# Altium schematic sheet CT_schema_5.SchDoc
size 300 x 247 mm
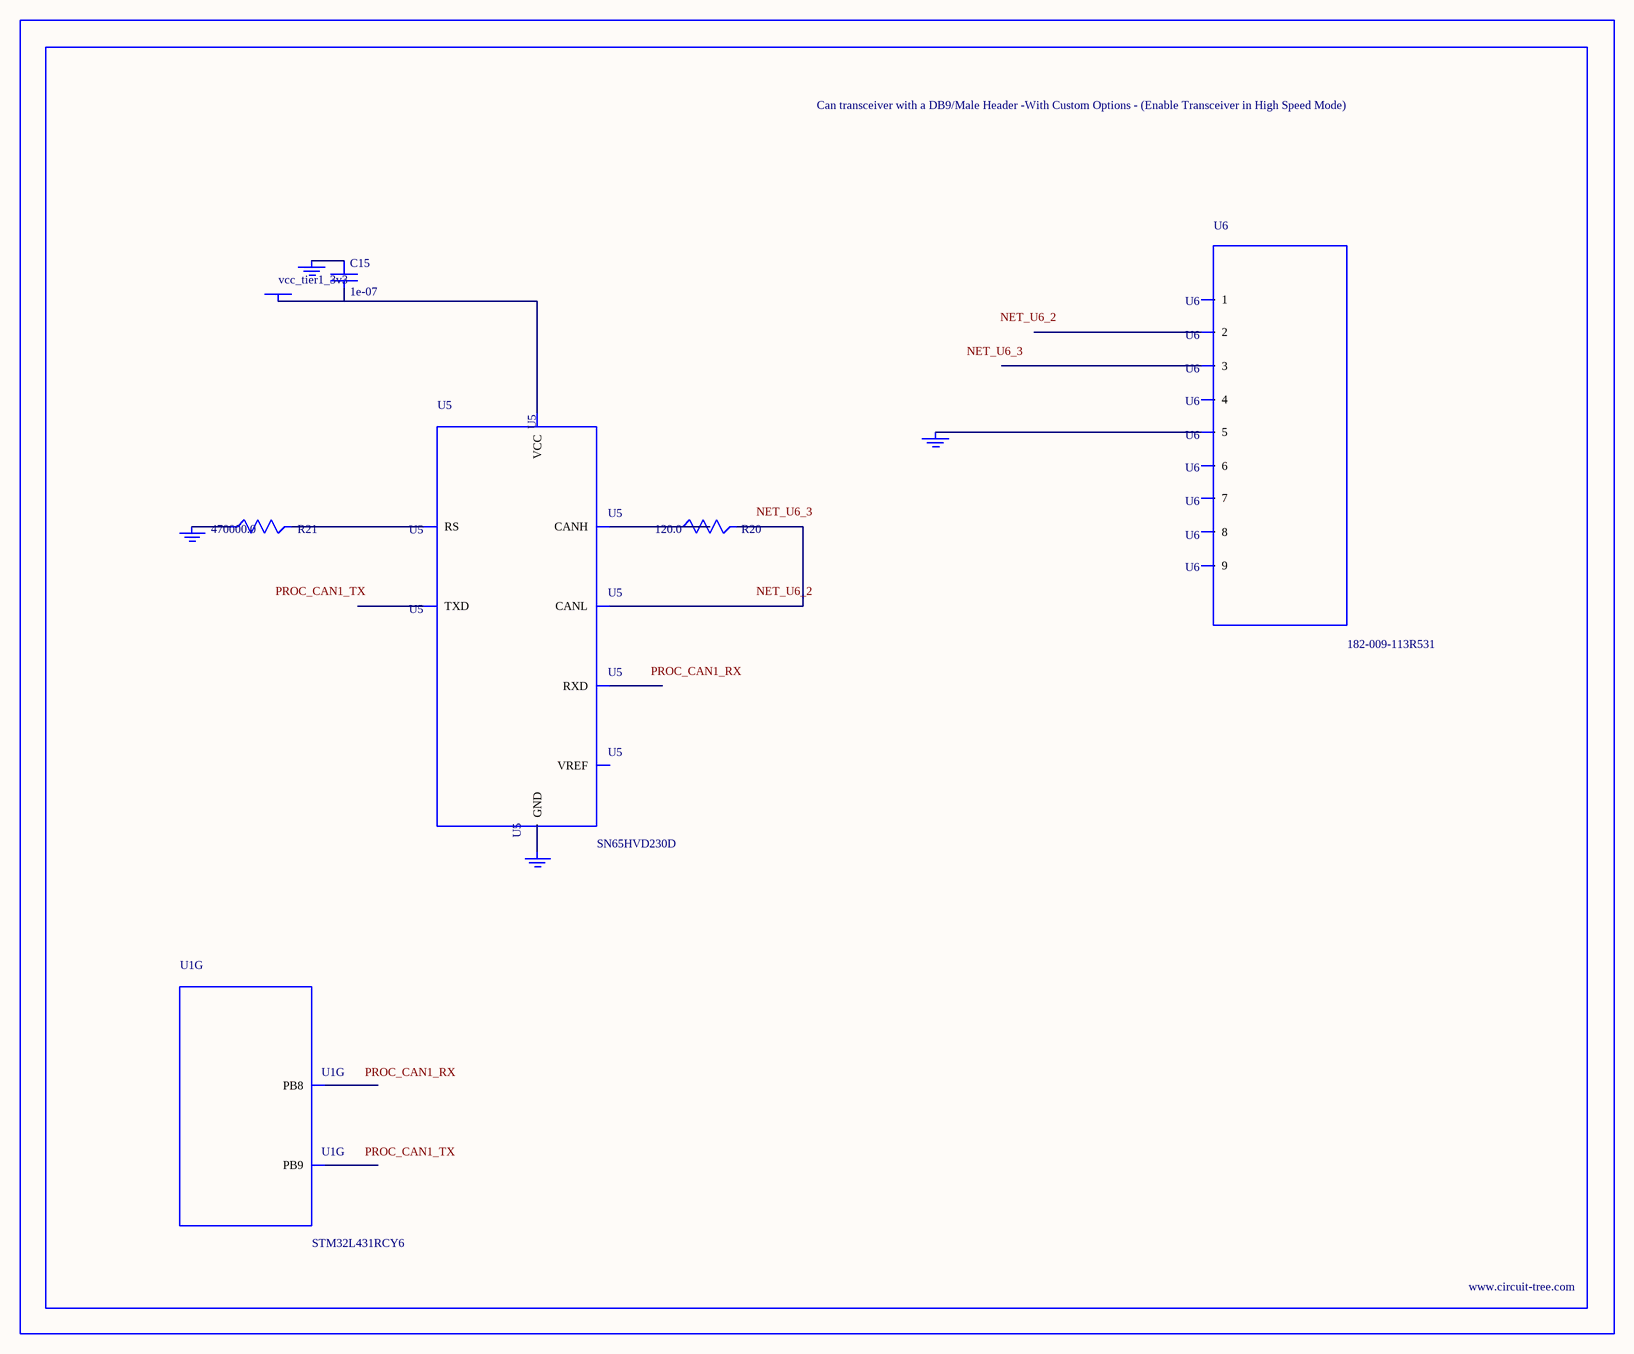
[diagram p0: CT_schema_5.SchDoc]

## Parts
BORDER4  (no value)
C15  1e-07  [C0402]
GND_INSTANCE_4_0  (no value)
GND_INSTANCE_4_1  (no value)
GND_INSTANCE_4_2  (no value)
GND_INSTANCE_4_3  (no value)
POWER_INSTANCE_4_0  vcc_tier1_3v3
R20  120.0  [R0603]
R21  470000.0  [R0603]
U1  STM32L431RCY6  [WLCSP64]  (part G of 8)
U5  SN65HVD230D  [SOIC-8]
U6  182-009-113R531  [182-009-MALE]

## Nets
NetC15_1: C15.1 GND_INSTANCE_4_0.0(GND)
NetC15_2: C15.2 POWER_INSTANCE_4_0.0(PWR) U5.3(VCC)
NetGND_INSTANCE_4_1_0: GND_INSTANCE_4_1.0(GND) R21.1
NetGND_INSTANCE_4_2_0: GND_INSTANCE_4_2.0(GND) U5.2(GND)
NetGND_INSTANCE_4_3_0: GND_INSTANCE_4_3.0(GND) U6.5
NetR20_1: R20.1 U5.7(CANH)
NetR20_2: R20.2 U5.6(CANL)
NetR21_2: R21.2 U5.8(RS)

Not connected (* = marked no-connect by the designer): U1 B6(PB9) C6(PB8); U5 1(TXD) 4(RXD) 5(VREF); U6 1 2 3 4 6 7 8 9

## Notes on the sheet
- Labels drawn without touching a wire or pin: NET_U6_2, NET_U6_3, PROC_CAN1_RX, PROC_CAN1_TX

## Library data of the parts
BORDER4 = BORDER_PAGE4
C15 = C0402C104K3RACTU
GND_INSTANCE_4_0-GND_INSTANCE_4_3 = GND
POWER_INSTANCE_4_0 = PWR
R20 = RC0603JR-07120RL
R21 = RC0603JR-07470KL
